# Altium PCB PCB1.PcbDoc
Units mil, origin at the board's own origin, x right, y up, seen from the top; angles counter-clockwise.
Board outline 4190.03 x 4245.03 mil, 2 copper layers (Top Layer, Bottom Layer); 62 components, 61 nets, 245 pads, 35 vias.
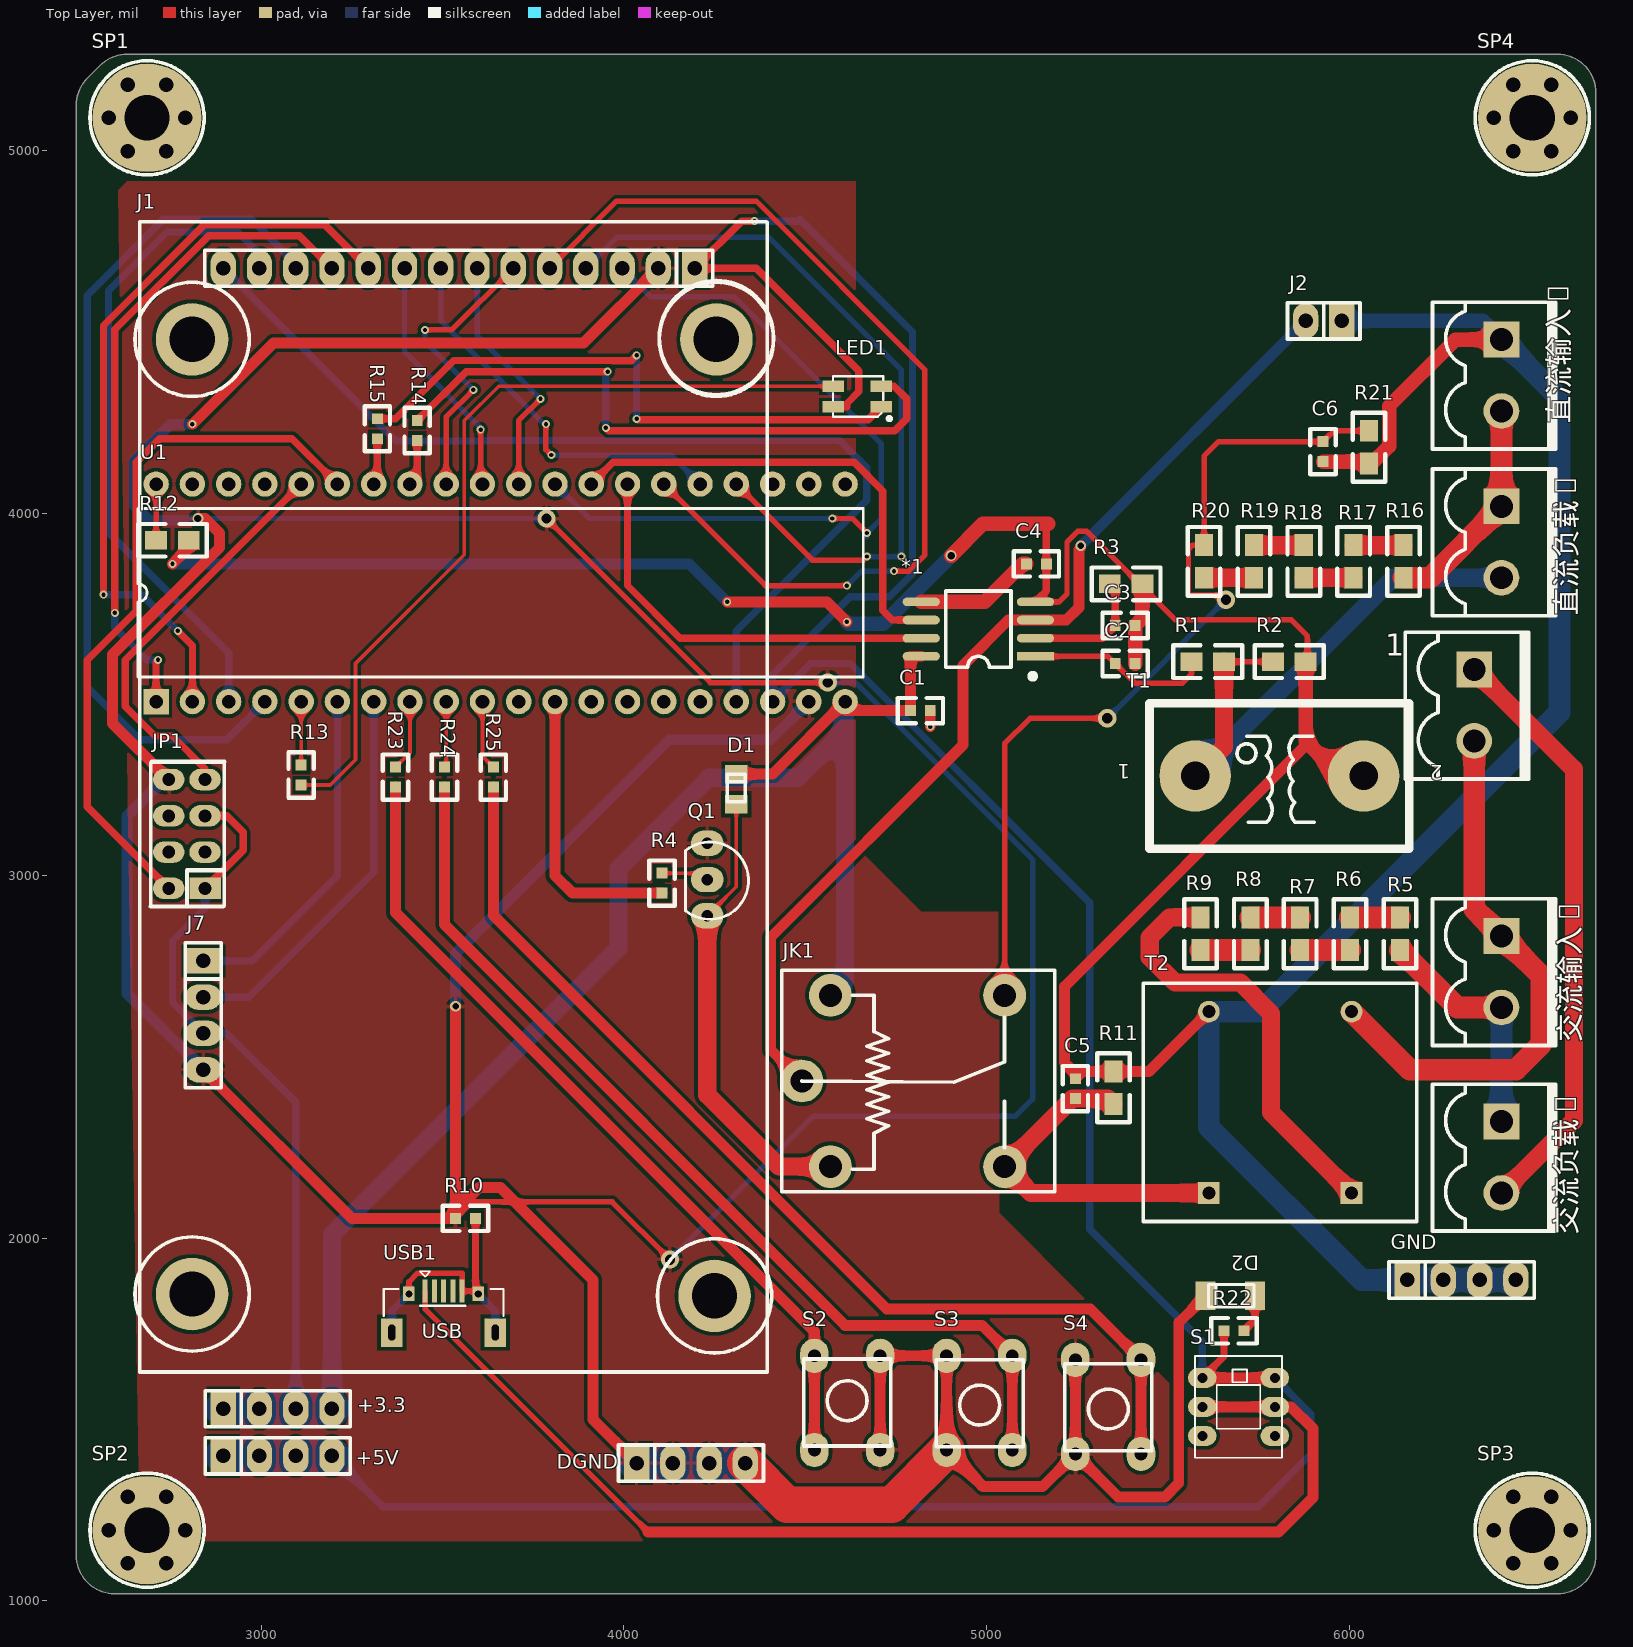
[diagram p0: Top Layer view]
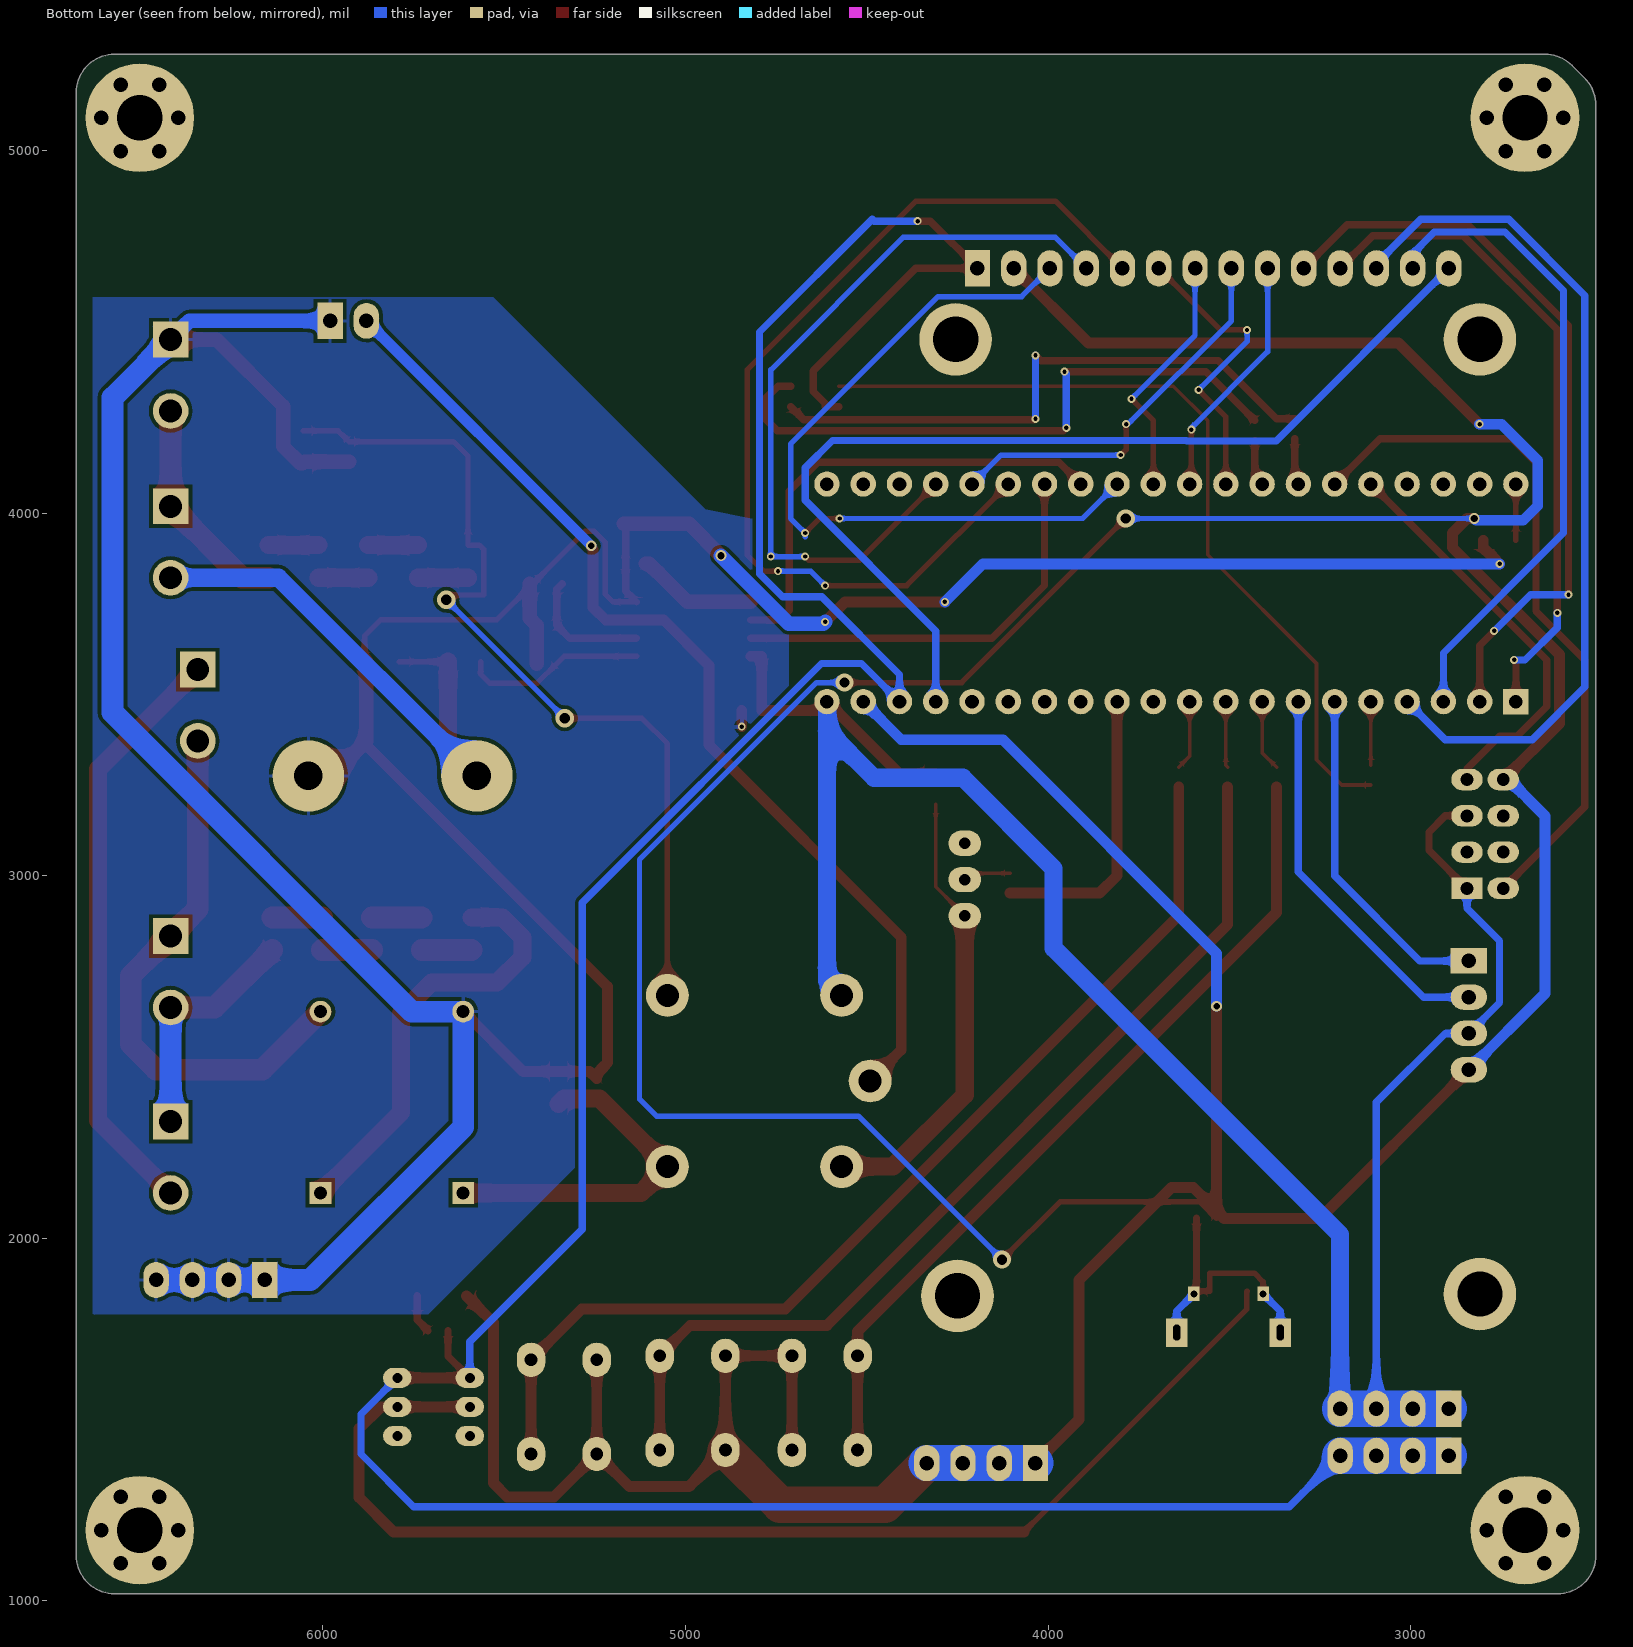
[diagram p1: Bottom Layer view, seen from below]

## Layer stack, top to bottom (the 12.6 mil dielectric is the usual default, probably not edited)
Top Solder: solder mask 0.4, Solder Resist, Dk 3.5
Top Layer: signal copper 1.4
Dielectric 1: dielectric 12.6, FR-4, Dk 4.8
Bottom Layer: signal copper 1.4
Bottom Solder: solder mask 0.4, Solder Resist, Dk 3.5

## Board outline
2489.99,1125 2489.99,5125.38 cw(c2595,5125.38) 2520.74,5199.63 2555.37,5234.26 cw(c2629.62,5160) 2629.62,5265.02 6575,5265.02 cw(c6575,5160) 6680.02,5160 6680.02,1125 cw(c6575,1125) 6575,1019.99 2595,1019.99 cw(c2595,1125)

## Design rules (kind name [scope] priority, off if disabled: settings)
Clearance [All] p1: gap=10 ignorepadtopadclearanceinfootprint=FALSE except(0: Arc-Hole Track-Hole SMDPad-Hole THPad-Hole Via-Hole Fill-Hole Poly-Hole Region-Hole Text-Hole)
PolygonConnect [All] p1: connectstyle=Relief reliefconductorwidth=10 reliefentries=4 polygonreliefangle="90 Angle" airgapwidth=10
RoutingVias [All] p1: holewidth=28 width=50 viastyle="Through Hole" minholewidth=28 minwidth=50 maxholewidth=28 maxwidth=50
SolderMaskExpansion [All] p1: expansion=4
Width [All] p1: maxlimit=100 minlimit=10 preferedwidth=15
30 further rules are at their usual default settings.

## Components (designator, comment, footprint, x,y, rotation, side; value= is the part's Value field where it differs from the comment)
1 "导线" KF2EDGK5.0-LI-2P 6345,3470 r270 top
*1 "HLW8110" SOP8W_M 4977.52,3680 r180 top
+3.3 "CON4" sip-4 2895,1530 r0 top
+5V "CON4" sip-4 2895,1400 r0 top
C1 "0.1uf" 0603 4845,3455 r180 top
C2 "330nf" 0603 5355,3585 r0 top
C3 "330nf" 0603 5410,3690 r180 top
C4 "0.1uf" 0603 5110,3860 r0 top
C5 "33nf" 0603 5245,2385 r90 top
C6 "33nf" 0603 5928,4196.82 r270 top
D1 "1N4007" LED_0805 4310,3239.29 r90 top
D2 "LED" LED_1206 5672,1841.3 r180 top
DGND "CON4" sip-4 4035,1380 r0 top
GND "CON4" sip-4 6160,1885 r0 top
J1 "CON14" 2.4TFT 3495,1791.3 r180 top
J2 "测量点" sip-2 5980,4530 r180 top
J7 "CON4" sip-4 2840,2765 r270 top
JK1 "SRD-05VDC-SL-C" SRD-C_B 4569.69,2670 r0 top
JP1 "HEADER 4X2" IDC-8 2845,2965 r90 top
LED1 "RGB-3528" "LED 3528-4Pin" 4643.5,4321.46 r180 top
Q1 "SS8050" TO92A 4230,3089.29 r0 top
R1 "100R" 0805 5655,3590 r180 top
R2 "10R" 0805 5880,3590 r180 top
R3 "100R" 0805 5430,3805 r180 top
R4 "510" 0603 4105,2951.85 r90 top
R5 "20k" 0805 6140,2795 r90 top
R6 "20k" 0805 6002.5,2885 r270 top
R7 "20k" 0805 5865,2795 r90 top
R8 "20k" 0805 5727.5,2885 r270 top
R9 "20k" 0805 5590,2795 r90 top
R10 "0R" 0603 3535.71,2055 r0 top
R11 "100R" 0805 5350,2460 r270 top
R12 "0R" 0805 2800,3925 r180 top
R13 "510" 0603 3110,3305 r270 top
R14 "510" 0603 3430,4200 r90 top
R15 "310" 0603 3320,4205 r90 top
R16 "20K" 0805 6150,3821.57 r90 top
R17 "20K" 0805 6012.5,3911.57 r270 top
R18 "20K" 0805 5875,3821.57 r90 top
R19 "20K" 0805 5737.5,3911.57 r270 top
R20 "20K" 0805 5600,3821.57 r90 top
R21 "1k" 0805 6055,4136.82 r90 top
R22 "510" 0603 5655,1745 r0 top
R23 "510" 0603 3370,3299.29 r270 top
R24 "510" 0603 3505,3299.29 r270 top
R25 "510" 0603 3640,3299.29 r270 top
S1 "SW-DPDT" SWH7*7 5595,1455 r90 top
S2 "SW-PB" SW6*6 4525.41,1416.16 r90 top
S3 "SW-PB" SW6*6 5071.1,1676 r270 top
S4 "SW-PB" SW6*6 5426.1,1665 r270 top
SP1 "M3铜柱" M3x4+6_N 2685,5090 r0 top
SP2 "M3铜柱" M3x4+6_N 2685,1195 r0 top
SP3 "M3铜柱" M3x4+6_N 6505,1195 r0 top
SP4 "M3铜柱" M3x4+6_N 6505,5090 r0 top
T1 "Current transformer" ZMCT103E 5575.43,3275 r180 top
T2 "DA101C" ZMPT101B 5810,2375 r180 top
U1 "STM32F103C8T6核心板" STM32F103C8T6核心板 3650,3885 r90 top
USB1 "USB-5P" USB-MICRO_A 3502.72,1740 r0 top
交流负载1 "负载" KF2EDGK5.0-LI-2P 6420,2223.43 r270 top
交流输入1 "AC_IN" KF2EDGK5.0-LI-2P 6420,2735 r270 top
直流负载1 "负载" KF2EDGK5.0-LI-2P 6420,3920 r270 top
直流输入1 "DC-IN" KF2EDGK5.0-LI-2P 6420,4380 r270 top

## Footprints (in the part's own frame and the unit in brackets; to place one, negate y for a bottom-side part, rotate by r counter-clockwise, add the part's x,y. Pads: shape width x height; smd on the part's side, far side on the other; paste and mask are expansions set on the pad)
2.4TFT [mil]
  round 200 hole 125: 0(-760,-2687.79) 0(-755,-50) 0(685.67,-55) 0(685.67,-2687.79)
  oval 70x100 hole 40: 1(600,-2883.7) 2(500,-2883.7) 3(400,-2883.7) 4(300,-2883.7) 5(200,-2883.7) 6(100,-2883.7) 7(0,-2883.7) 8(-100,-2883.7) 9(-200,-2883.7) 10(-300,-2883.7) 11(-400,-2883.7) 12(-500,-2883.7) 13(-600,-2883.7)
  rect 70x100 hole 40: 14(-700,-2883.7)
  silkscreen extent -917,-3012 843,160, body extent -866,-2785 792,43, height 159
0603 [mil]
  rect 30x30 smd: 1(0,0) 2(55,0)
  silkscreen extent -35,-35 90,35
0805 [mil]
  rect 60x50 smd: 1(0,0) 2(90,0)
  silkscreen extent -50,-45 140,45
IDC-8 [mm]
  rect 1.5x2.2 hole 0.9: 1(0,0)
  oval 1.5x2.2 hole 0.9: 2(0,2.54) 3(2.54,0) 4(2.54,2.54) 5(5.08,0) 6(5.08,2.54) 7(7.62,0) 8(7.62,2.54)
  silkscreen extent -1.27,-1.36 8.88,3.81
KF2EDGK5.0-LI-2P [mm] "立插端子                  淘宝ID:黄晶宝石"
  rect 2.5x2.5 hole 1.6: 1(-2.5,0)
  round 2.5 hole 1.6: 2(2.5,0)
  silkscreen extent -5.12,-4.83 5.17,3.81, body extent -5.04,-4.75 5.04,3.75, height 11.25
"LED 3528-4Pin" [mm] "4脚，3528LED                             淘宝ID:黄晶宝石"
  rect 1.5x0.8 smd: 1(-1.689,0.725) 2(-1.689,-0.725) 3(1.689,-0.725) 4(1.689,0.725)
  silkscreen extent -2.37,-1.42 1.69,1.68, body extent -1.75,-1.4 1.75,1.4, height 1.95
LED_0805 [mm]
  rect 1.3x1.6 smd: 1(-1.067,0) 2(1.041,0)
  silkscreen extent -0.89,-0.64 1.02,0.64
LED_1206 [mm]
  rect 1.4x2 smd: 1(-1.727,0) 2(1.727,0)
  silkscreen extent -1.68,-0.79 1.52,0.79, body extent -1.65,-0.79 1.55,0.81, height 1.11
M3x4+6_N [mil] "M3铜柱，长：4mm，螺纹长：6mm"
  round 40 hole 40: 1(-106,0) 1(-53,-91.8) 1(-53,91.8) 1(53,-91.8) 1(53,91.8) 1(106,0)
  round 300 hole 125: 1(0,0)
  silkscreen extent -157,-157 157,157, body extent -106,-93 106,93, height 159
sip-2 [mil]
  rect 70x100 hole 40: 1(0,0)
  oval 70x98.42 hole 40: 2(100,0)
  silkscreen extent -50,-50 150,50
sip-4 [mil]
  rect 70x100 hole 40: 1(0,0)
  oval 70x100 hole 40: 2(100,0) 3(200,0) 4(300,0)
  silkscreen extent -50,-50 350,50
SOP8W_M [mm] "5.3*8.3*1.8mm（长宽高）  淘宝ID:黄晶宝石"
  rect 2.6x0.6 smd: 1(-4,1.905)
  oval 2.6x0.6 smd: 2(-4,0.635) 3(-4,-0.635) 4(-4,-1.905) 5(4,-1.905) 6(4,-0.635) 7(4,0.635) 8(4,1.905)
  silkscreen extent -3.94,-2.67 2.29,3.43, body extent -3.94,-2.64 3.94,2.64, height 1.9
SRD-C_B [mm] "单刀双投                  淘宝ID:黄晶宝石"
  round 3 hole 1.6: 1(0,0) 2(0,-12) 3(-2,-6) 4(12.2,0) 5(12.2,-12)
  silkscreen extent -3.4,-13.75 15.7,1.75, body extent -3.4,-13.75 15.7,1.75, height 15.6
STM32F103C8T6核心板 [mil]
  round 70 hole 37.4: 1(195,940) 2(195,840) 3(195,740) 4(195,640) 5(195,540) 6(195,440) 7(195,340) 8(195,240) 9(195,140) 10(195,40) 11(195,-60) 12(195,-160) 13(195,-260) 14(195,-360) 15(195,-460) 16(195,-560) 17(195,-660) 18(195,-760) 19(195,-860) 20(195,-960) 21(-405,-960) 22(-405,-860) 23(-405,-760) 24(-405,-660) 25(-405,-560) 26(-405,-460) 27(-405,-360) 28(-405,-260) 29(-405,-160) 30(-405,-60) 31(-405,40) 32(-405,140) 33(-405,240) 34(-405,340) 35(-405,440) 36(-405,540) 37(-405,640) 38(-405,740) 39(-405,840)
  rect 70x70 hole 37.4: 40(-405,940)
  silkscreen extent -337,-1010 127,990
SW6*6 [mm]
  oval 2.4x2 hole 0.9: 1(0,0) 1(6.6,0) 2(0,-4.6) 2(6.6,-4.6)
  silkscreen extent 0.28,-5.34 6.38,0.76
SWH7*7 [mm]
  oval 1.4x2 hole 0.7: 1(0,0) 2(2.032,0) 3(4.064,0) 4(4.064,-5.08) 5(2.032,-5.08) 6(0,-5.08)
  silkscreen extent -1.52,-5.59 5.59,0.51
TO92A [mil]
  oval 90x70 hole 31.5: 1(0,0) 2(0,-100) 3(0,-200)
  silkscreen extent -60,-209 114,4
USB-MICRO_A [mm] "micro型USB ，5.7*7.8*2.5mm"
  rect 0.35x1.6 smd: 1(-1.3,2.9) 2(-0.65,2.9) 3(0,2.9) 4(0.65,2.9) 5(1.3,2.9)
  rect 1.5x2 hole 0.5 slot 1.1 at 90 deg: 5(-3.625,0) 5(3.625,0)
  rect 0.8x1 hole 0.5: 5(-2.425,2.71) 5(2.425,2.71)
  silkscreen extent -4.19,-2.79 4.19,4.3, body extent -4,-2.71 4,2.89, height 2.8
ZMCT103E [mm] "102mm*182mm"
  round 5 hole 2: 1(0,0) 2(-11.8,0)
  silkscreen extent -15,-5.1 3.2,5.1
ZMPT101B [mil]
  rect 60x60 hole 35.98: 1(-196.85,250) 3(196.85,250)
  round 60 hole 35.98: 2(-196.85,-250) 4(196.85,-250)
  silkscreen extent -376,-329 378,329

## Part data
1 R1 R2 R3 R4 R5 R6 R7 R8 R9 R10 R11 R12 R13 R14 R15 R16 R17 R18 R19 R20 R21 R22 R23 R24 R25 交流负载1 直流负载1: library part RES, "电阻"
+3.3 +5V DGND GND J1 J7: "Connector"
C1 C2 C3 C4 C5 C6: library part CAP1
D1: library part DIODE
J2 交流输入1 直流输入1: library part CON2, "Connector"
JK1: "5V一组转换"
LED1: library part "LED-RGB 3528", "3528三基色LED"
Q1: library part 8050-DIP, "高频放大-NPN型"
SP1 SP2 SP3 SP4: library part 铜柱加头大焊盘, "铜柱"
T2: library part DA10XC, "数字隔离变压器"
USB1: "微型USB母座"

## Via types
v1: diameter 22, hole 12, Top Layer to Bottom Layer, 26 vias
v2: diameter 50, hole 28, Top Layer to Bottom Layer, 5 vias
v3: diameter 30, hole 20, Top Layer to Bottom Layer, 2 vias
v4: diameter 30, hole 18, Top Layer to Bottom Layer, 2 vias

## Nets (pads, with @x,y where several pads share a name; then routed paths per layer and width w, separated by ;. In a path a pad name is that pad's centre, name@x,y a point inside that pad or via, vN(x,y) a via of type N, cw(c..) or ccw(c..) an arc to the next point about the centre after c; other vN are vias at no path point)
+3.3V: *1.8 +3.3.1 +3.3.2 +3.3.3 +3.3.4 C1.2 D1.2 J7.3 JK1.1 JP1.1 JP1.5 U1.21 | length 6467.4
  Top Layer w20: JP1.1 2950,3070 2950,3120 2905,3165 JP1.5
  Top Layer w30: D1.2 4410.29,3280.29 U1.21 4610,3455 C1.2 4790,3605 *1.8
  Bottom Layer w20: JP1.1 2845,2910 2755,2820 2755,2650 J7.3 2905,2565 3095,2375 +3.3.3
  Bottom Layer w50: +3.3.4 3195,2010 3985,2800 3985,3020 4235,3270 4480,3270 4610,3400 ; JK1.1 4610,2710.32 4610,3400 ; U1.21 4610,3400
  Bottom Layer w100: +3.3.1 +3.3.2 +3.3.3 +3.3.4
+5V: +5V.1 +5V.2 +5V.3 +5V.4 J1.14 LED1.4 R22.1 S1.3 S1.4 U1.23 | length 9103.7
  Top Layer w20: v1(4360,4805) 4325,4805 J1.14 4365,4675 4647.91,4392.09 4647.91,4335 4615,4302.09 4615,4292.91 LED1.4 ; S1.3 5655,1675 R22.1
  Top Layer w30: S1.3 S1.4
  Bottom Layer w20: +5V.4 3335,1260 5750,1260 5895,1405 5895,1515 S1.4 ; v1(4360,4805) 4480,4805 4485,4810 4796,4499 4796,3832.57 4732.43,3769 4624,3769 4410,3555 U1.23 4515,3585 4625,3585 5285,2925 5285,2025 5595,1715 S1.3
  Bottom Layer w100: +5V.1 +5V.2 +5V.3 +5V.4
AC_C: C5.1 JK1.5 R11.2 T2.3 | length 977.1
  Top Layer w50: R11.2 5335,2385 C5.1 5237.44,2385 JK1.5 5122.56,2125 T2.3
connect_1: R1.1 R2.2 T1.1 直流负载1.2 | length 1553.9
  Top Layer w15: R1.1 R2.2
  Top Layer w50: T1.1 5655,3354.57 R1.1
  Bottom Layer w50: T1.1 6122.01,3821.57 直流负载1.2
CS: J1.12 U1.12 | length 2103.5
  Top Layer w15: v1(4575,3985) 4630,3985 v1(4670,3945)
  Bottom Layer w15: U1.12 3905,3985 v1(4575,3985) ; J1.12 4073.41,4596.59 4303.67,4596.59 4710,4190.26 4710,3985 v1(4670,3945) v1@4670,3935
DC: J1.10 U1.15 | length 2685.4
  Top Layer w15: J1.10 3980,4860 4365,4860 4830,4395 4830,3885 4785,3840 v1(4745,3840) ; U1.15 4390,3800 v1(4615,3800)
  Bottom Layer w15: v1(4615,3800) 4655,3840 v1(4745,3840)
DC_C: C6.1 JK1.4 R20.2 R21.2 | length 2479.8
  Top Layer w15: JK1.4 5050,3364 5120,3434 v2(5333,3434) ; v2(5660,3761) 5646.93,3774.07 5557,3774.07 5557,3900 5568.57,3911.57 R20.2 5600,4156.82 5640,4196.82 C6.1 5958,4226.82 R21.2
  Bottom Layer w15: v2(5333,3434) v2(5660,3761)
DGND: D2.2 DGND.1 DGND.2 DGND.3 DGND.4 J1.13 J7.4 JP1.8 Q1.1 R10.1 S2.2 S3.2 S4.2 U1.22 | length 16252.8
  Top Layer w15: R10.1 3581.42,2100.71 3967.29,2100.71 v2(4127,1941) ; v2(3786.11,3985) 4238.61,3532.5 v2(4562,3532.5)
  Top Layer w30: JP1.8 2590,3420 2590,3609.5 2885,3904.5 2885,3945 2845,3985 v3(2825,3985) ; v1(2810,4245) 3034,4469 3889,4469 J1.13 J1.13@4100,4680 ; J7.4 3250,2055 3515,2055 3535.71,2075.71 ; v4(3535.71,2640) 3535.71,2075.71 ; DGND.1 3915,1500 3915,1885 3660,2140 3600,2140 3535.71,2075.71 ; S2.2@4706.51,1416.16 4706.51,1676 4890,1676 4890,1416.16 4991.16,1315 5154.84,1315 S4.2@5245,1405.16 ; S4.2@5245,1665 S4.2@5245,1405.16 ; D2.2 5530,1767.3 5530,1325 5491.8,1286.8 5363.36,1286.8 S4.2@5245,1405.16
  Top Layer w100: DGND.4 4450,1265 4738.84,1265 S3.2@4890,1416.16
  Bottom Layer w15: v3(2825,3985) v2(3786.11,3985) ; v2(4127,1941) 4523,2337 5080,2337 5127,2384 5127,3044.11 4638.61,3532.5 v2(4562,3532.5)
  Bottom Layer w30: JP1.8 2730,3265 2630,3165 2630,2675 J7.4 ; v1(2810,4245) 2750,4245 2650,4145 2650,4020 2690,3980 v3@2820,3980 ; v4(3535.71,2640) 3535.71,2785.71 4125,3375 4405,3375 U1.22
  Bottom Layer w100: DGND.1 DGND.2 DGND.3 DGND.4
GND: *1.4 C1.1 C2.2 C3.1 C4.2 C5.2 C6.2 GND.1 GND.2 GND.3 GND.4 J2.1 R2.1 R3.1 R11.1 R12.1 R21.1 T1.2 T2.4 直流输入1.1 | length 11489.7
  Top Layer w15: *1.4 5200,3755 5222,3777 5222,3920 5252,3950 5276,3950 5520,3706 5840,3706 5885,3661 5885,3595 5885,3375
  Top Layer w20: *1.4 5165,3785 C4.2 5165,3965 5170,3970
  Top Layer w30: v1(2755,3860) 2800,3905 R12.1 ; v1(4285,3755) 4560,3755 v1(4615,3700) ; v1(4845,3410.86) C1.1 ; C5.2 5265,2460 R11.1 5448.15,2460 T2.4 ; C5.2@5245,2454.29 5215,2484.29 5215,2693.9 5880,3358.9 5880,3370 5885,3375
  Top Layer w40: v3(4902.5,3882.5) 4990,3970 5170,3970 ; C2.2 C3.1 5430,3710 R3.1 ; R2.1@5885,3595 R2.1 5880,3370 5975,3275 T1.2 ; C6.2 6050,4141.82 R21.1 6062.43,4136.82 6110,4184.39 6110,4295.14 6293.29,4478.43 直流输入1.1
  Bottom Layer w30: v1(2755,3860) 4180,3860 v1(4285,3755)
  Bottom Layer w40: v1(4615,3700) 4620,3695 4715,3695 v3(4902.5,3882.5) ; J2.1 6368.43,4530 直流输入1.1
  Bottom Layer w60: 直流输入1.1 6580,4318.43 6580,3450 5755,2625 T2.4 5613.15,2306.85 6035,1885 GND.1 GND.2 GND.3 GND.4
L: R5.1 交流负载1.1 交流输入1.2 | length 660.3
  Top Layer w60: R5.1 6298.43,2636.57 交流输入1.2
  Bottom Layer w60: 交流负载1.1 交流输入1.2
LED_BACK: J1.7 U1.16 | length 1087.4
  Top Layer w15: v1(3785,4245) 3785,4175 v1(3800,4160)
  Bottom Layer w15: J1.7 3495,4530 3780,4245 v1(3785,4245) ; v1(3800,4160) 4130,4160 U1.16
MISO: J1.6 U1.10 | length 684.1
  Top Layer w15: v1(3605,4230) 3605,4085 U1.10
  Bottom Layer w15: J1.6 3395,4445 3605,4235 v1(3605,4230)
MOSI: J1.9 U1.9 | length 825.2
  Top Layer w15: v1(3451.54,4505) 3525,4505 J1.9 ; U1.9 3510,4265 v1(3585,4340)
  Bottom Layer w15: v1(3451.54,4505) 3451.54,4473.46 v1(3585,4340)
N: 1.2 T2.2 交流输入1.1 | length 1531.6
  Top Layer w60: T2.2 6166.85,2465 6460,2465 6530,2535 6530,2723.43 交流输入1.1 6345,2908.43 1.2
Net1_1: 1.1 交流负载1.2 | length 1640.2
  Top Layer w50: 1.1 6620,3293.43 6620,2325 交流负载1.2
Net*1_1: *1.1 C2.1 R1.2 | length 505
  Top Layer w15: *1.1 5335.01,3605 C2.1 5409,3531 5540,3531 5565,3556 R1.2
Net*1_2: *1.2 C3.2 R3.2 | length 355.7
  Top Layer w20: *1.2 5320,3655 C3.2 5355,3790 R3.2
Net*1_3: *1.3 J2.2 JK1.3 | length 2836.5
  Top Layer w30: JK1.3 4405,2519.72 4405,2830 4935,3360 4935,3580 5060,3705 *1.3 5220,3705 5255,3740 5255,3900 5260,3905 v4(5260,3910)
  Bottom Layer w30: v4(5260,3910) J2.2
Net*1_5: *1.5 C4.1 | length 333.5
  Top Layer w40: *1.5 4995,3755 5100,3860 C4.1
NetD1_1: D1.1 JK1.2 Q1.3 | length 1256.9
  Top Layer w10: Q1.3 4310,2969.29 D1.1
  Top Layer w50: Q1.3 4230,2395 4427.44,2197.56 JK1.2
NetD2_1: D2.1 R22.2 | length 108.7
  Top Layer w20: R22.2 5740,1775 D2.1
NetLED1_1: LED1.1 R15.2 | length 1654.3
  Top Layer w20: R15.2 3370,4260 3531,4421 3967.84,4421 3968.84,4420 4020,4420 v1(4035,4435) ; v1(4035,4260) 4037.84,4257.17 4674.25,4257.17 LED1.1
  Bottom Layer w20: v1(4035,4260) v1(4035,4435)
NetLED1_2: LED1.2 R14.2 | length 1724.3
  Top Layer w20: R14.2 3565,4390 v1(3955,4390) ; v1(3950,4235) 3957.83,4227.17 4747.17,4227.17 4780,4260 4780,4315 4745,4350 LED1.2
  Bottom Layer w20: v1(3950,4235) 3950,4385 v1(3955,4390)
NetLED1_3: LED1.3 R13.2 | length 2294.6
  Top Layer w10: R13.2 3190,3250 3260,3320 3260,3585 3560,3885 3560,4255 3655,4350 LED1.3
NetQ1_2: Q1.2 R4.2 | length 132.3
  Top Layer w10: R4.2 4212.44,3006.85 Q1.2
NetR5_2: R5.2 R6.1 | length 137.5
  Top Layer w60: R6.1 R5.2
NetR6_2: R6.2 R7.1 | length 137.5
  Top Layer w60: R7.1 R6.2
NetR7_2: R7.2 R8.1 | length 137.5
  Top Layer w60: R8.1 R7.2
NetR8_2: R8.2 R9.1 | length 137.5
  Top Layer w60: R9.1 R8.2
NetR9_2: R9.2 T2.1 | length 1203.9
  Top Layer w50: R9.2 5505,2885 5450,2830 5450,2775 5520,2705 5700,2705 5785,2620 5785,2346.85 T2.1
NetR10_2: R10.2 USB1.5 | length 740.5
  Top Layer w15: USB1.5@3407.24,1846.69 3407.24,1880 3431.24,1904 3553.9,1904 3553.9,1854.17 USB1.5@3590.71,1854.17
  Top Layer w20: R10.2 3590.71,1854.17 USB1.5@3598.19,1846.69
  Bottom Layer w20: USB1.5@3360,1740 3360,1799.45 USB1.5@3407.24,1846.69 ; USB1.5@3598.19,1846.69 3645.43,1799.45 USB1.5@3645.43,1740
NetR12_2: R12.2 U1.1 | length 155
  Top Layer w15: R12.2 U1.1
NetR16_1: R16.1 直流负载1.1 直流输入1.2 | length 614.7
  Top Layer w60: R16.1 6223.15,3821.57 直流负载1.1 直流输入1.2
NetR16_2: R16.2 R17.1 | length 137.5
  Top Layer w50: R17.1 R16.2
NetR17_2: R17.2 R18.1 | length 137.5
  Top Layer w50: R18.1 R17.2
NetR18_2: R18.2 R19.1 | length 137.5
  Top Layer w50: R19.1 R18.2
NetR19_2: R19.2 R20.1 | length 137.5
  Top Layer w50: R20.1 R19.2
NetR23_2: R23.2 S2.1 | length 2306.7
  Top Layer w30: R23.2 3370,2898.08 4525.41,1742.67 4525.41,1676 S2.1@4525.41,1416.16
NetR24_2: R24.2 S3.1 | length 2697.7
  Top Layer w30: R24.2 3505,2865 4610,1760 4987.1,1760 5071.1,1676 S3.1@5071.1,1416.16
NetR25_2: R25.2 S4.1 | length 2907.6
  Top Layer w30: R25.2 3640,2890 4725,1805 5286.1,1805 5426.1,1665 S4.1@5426.1,1405.16
PA11: R23.1 U1.33 | length 197.3
  Top Layer w10: R23.1 3410,3339.29 U1.33
PA12: R24.1 U1.32 | length 182.8
  Top Layer w10: R24.1 3510,3304.29 U1.32
PA15: R25.1 U1.31 | length 193.1
  Top Layer w10: U1.31 3610,3329.29 R25.1
PB4: R4.1 U1.29 | length 794.9
  Top Layer w30: U1.29 3810,3000 3858.15,2951.85 R4.1
Power_In: S1.2 S1.5 USB1.1 | length 3311.5
  Top Layer w15: USB1.1 3452.74,1852.97 3452.74,1803.98 4066.72,1190
  Top Layer w30: 4066.72,1190 5805,1190 5900,1285 5900,1475 5840,1535 S1.5 S1.2
RST: J1.11 U1.17 | length 2126.7
  Top Layer w15: U1.17 4520,3870 4660,3870 v1(4670,3880)
  Bottom Layer w15: J1.11@3895,4670 J1.11 3980,4760 4400,4760 4765,4395 v1(4765,3880) 4760,3885 4755,3880 v1(4670,3880)
RX_measure: *1.6 U1.13 | length 1308.4
  Top Layer w20: U1.13 3970,4140 4635,4140 4714,4061 4714,3731 4740,3705 *1.6
RX_PC: J7.2 U1.34 | length 1082.9
  Bottom Layer w20: J7.2 2965,2665 3310,3010 U1.34
RX_WIFI: JP1.7 U1.5 | length 1135.3
  Top Layer w20: JP1.7 2845,3295 2755,3385 2706.72,3385 2625,3466.72 2625,3595 U1.5
SCK: J1.8 U1.11 | length 692.3
  Top Layer w15: U1.11 3710,4255 v1(3770,4315)
  Bottom Layer w15: J1.8 3595,4490 v1(3770,4315)
SPI2_MISO: J1.2 U1.38 | length 1818.6
  Bottom Layer w20: U1.38 2910,3614.33 2579,3945.33 2579,4614 2740,4775 2935,4775 2995,4715 J1.2
SPI2_MOSI: J1.3 U1.37 | length 2398.7
  Bottom Layer w20: U1.37 2905,3375 2665,3375 2520,3520 2520,4600 2730,4810 2972.43,4810 3095,4687.43 J1.3
SPI2_NSS: J1.4 U1.40 | length 1838.5
  Top Layer w20: v1(2596,3725) 2596,4506 2855,4765 3105,4765 J1.4 ; U1.40 2710,3590 v1(2715,3595)
  Bottom Layer w20: v1(2596,3725) 2596,3684 2685,3595 v1(2715,3595)
SPI2_SCK: J1.5 U1.39 | length 2095.1
  Top Layer w20: v1(2565,3775) 2565,4517.43 2842.57,4795 3175,4795 J1.5 ; v1(2770,3675) 2810,3635 U1.39
  Bottom Layer w20: v1(2565,3775) 2670,3775 v1(2770,3675)
TFT_PB9: J1.1 U1.24 | length 2797.8
  Bottom Layer w20: J1.1 3371,4199 3617.84,4199 3618.84,4200 4595,4200 4670,4125 4670,4035 4310,3675 U1.24
TIM1_CH1: R13.1 U1.36 | length 175
  Top Layer w10: R13.1 U1.36
TIM3_TH3: R14.1 U1.8 | length 128.3
  Top Layer w20: U1.8 3430,4100 R14.1
TIM3_TH4: R15.1 U1.7 | length 129.1
  Top Layer w20: U1.7 3320,4090 R15.1
TX_measure: *1.7 U1.14 | length 1150.1
  Top Layer w20: U1.14 4010,3800 4155,3655 *1.7
TX_PC: J7.1 U1.35 | length 947.3
  Bottom Layer w20: J7.1 2975,2765 3210,3000 U1.35
TX_WIFI: JP1.2 U1.6 | length 1957.8
  Top Layer w20: JP1.2 2520,3190 2520,3595 2655,3730 2655,4140 2720,4205 3085,4205 U1.6
pads on no net: J1.0 JP1.3 JP1.4 JP1.6 S1.1 S1.6 SP1.1 SP2.1 SP3.1 SP4.1 U1.2 U1.3 U1.4 U1.18 U1.19 U1.20 U1.25 U1.26 U1.27 U1.28 U1.30 USB1.2 USB1.3 USB1.4

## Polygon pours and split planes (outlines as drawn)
GND on Bottom Layer (solid, remove dead copper, pour order 18): 4945,4010 5530,4595 6635,4595 6635,1785 6630,1790 5710,1790 4715,2785 4715,3965
GND on Bottom Layer (solid, remove dead copper, pour order 16): 5035,4565
DGND on Top Layer (solid, remove dead copper, pour order 20): 2605,4890 2630,4915 4640,4915 4640,3080 4820,2900 5035,2900 5035,2070 5600,1505 5890,1505 5890,1245 5750,1105 5690,1165 2665,1165

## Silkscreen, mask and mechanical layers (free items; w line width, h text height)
Mechanical 1:
  lines w10: 2495,5075 2495,5125.38 cw(c2595,5125.38) 2524.29,5196.09 2558.91,5230.71 cw(c2629.62,5160) 2629.62,5260 2680,5260 6500,5260 6575,5260 cw(c6575,5160) 6675,5160 6675,5095 6675,1195 6675,1125 cw(c6575,1125) 6575,1025 6510,1025 2935,1025 2595,1025 cw(c2595,1125) 2495,1125 2495,1200 2495,5085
